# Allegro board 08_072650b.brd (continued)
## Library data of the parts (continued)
C121 C202 C203 C205 C207 C342 C347 C359 C364 C372 C376 C377 C383 C392 C399 C400 C407 C410 C417 C426 C427 C437 C446 C449 C455 C472 C473 C482-C484 C486-C489 C498-C501 C503-C507 C664 C667 C670 = CAP: Tolerance: 10; User Part Number: UPN; alternate symbols: (C0201L); part number: CAP_SM-1000PF,25V,10,E006762,C0201; tolerance: 10
C124 C141 C142 C144 C244 C246 C290 C605 = CAP: User Part Number: UPN; Tolerance: 10; alternate symbols: (C0402); part number: CAP_SM-0.1UF,16V,10,E028141,C0402; tolerance: 10
C126 = CAP: Tolerance: 5; User Part Number: UPN; alternate symbols: (C0402H22); part number: CAP_SM-160PF,50V,5,E025262,C0402H22; tolerance: 5
C127 C128 = CAP: User Part Number: UPN; Tolerance: 5; alternate symbols: (C0402); part number: CAP_SM-4700PF,10V,5,E021174,C0402; tolerance: 5
C133 C136 C193 = CAP: User Part Number: UPN; Tolerance: 20; alternate symbols: (C0402); part number: CAP_SM-10UF,6.3V,20,E025264,C0402; tolerance: 20
C135 C197 C198 C603 = CAP_SP: Tolerance: 20; User Part Number: UPN; alternate symbols: (C0805H60_SP); part number: CAP_SP_SM-22UF,16V,20,E048607,C0805H60_SP; tolerance: 20
C137-C139 C187-C189 C754-C756 = CAP: User Part Number: UPN; Tolerance: 20; alternate symbols: (C0805H60); part number: CAP_SM-47UF,6.3V,20,E025498,C0805H60; tolerance: 20
C140 C194 C601 = CAP: Tolerance: 20; User Part Number: UPN; alternate symbols: (C0402); part number: CAP_SM-10UF,6.3V,20,E025264,C0402; tolerance: 20
C153 C159 C524 C525 C614 = CAP: User Part Number: UPN; Tolerance: 10; alternate symbols: (C1206); part number: CAP_SM-10UF,16V,10,E043891,C1206; tolerance: 10
C157 = CAP: User Part Number: UPN; Tolerance: 20; alternate symbols: (C0402); part number: CAP_SM-1UF,10V,10,E028140,C0402; tolerance: 10
C158 = CAP: Tolerance: 20; User Part Number: UPN; alternate symbols: (C0402); part number: CAP_SM-1UF,10V,10,E028140,C0402; tolerance: 10
C160 C192 C617 = CAP: Tolerance: 10; User Part Number: UPN; alternate symbols: (C1206); part number: CAP_SM-10UF,16V,10,E043891,C1206; tolerance: 10
C161 C164 C170 C178 C180 C190 C528 C615 C853 = CAP: Tolerance: 20; User Part Number: UPN; alternate symbols: (C0805H53); part number: CAP_SM-100UF,6.3V,20,E029764,C0805H53; tolerance: 20
C162 C165 C529 C535 C609 = CAP: User Part Number: UPN; Tolerance: 20; alternate symbols: (C0805H53); part number: CAP_SM-100UF,6.3V,20,E029764,C0805H53; tolerance: 20
C177 C179 C181-C183 C236 C531 C534 C604 C610-C613 C616 = CAP: Tolerance: 20; User Part Number: UPN; alternate symbols: (C0805H60); part number: CAP_SM-47UF,6.3V,20,E025498,C0805H60; tolerance: 20
C184-C186 = CAP: User Part Number: UPN; Tolerance: 20; alternate symbols: (C0603); part number: CAP_SM-10UF,6.3V,20,E007143,C0603; tolerance: 20
C191 = CAP: Tolerance: 10; User Part Number: UPN; alternate symbols: (C0402); part number: CAP_SM-1UF,10V,10,E028140,C0402; tolerance: 10
C196 C602 = CAP: Tolerance: 20; User Part Number: UPN; alternate symbols: (C0402); part number: CAP_SM-4.7UF,6.3V,20,E014207,C0402; tolerance: 20
C199 C200 C249 C262-C264 C512-C516 = CAP: Tolerance: 10; User Part Number: UPN; alternate symbols: (C1210H106); part number: CAP_SM-22UF,25V,10,E054041,C1210H106; tolerance: 10
C224 C608 = CAP: User Part Number: UPN; Tolerance: 10; alternate symbols: (C0402L); part number: CAP_SM-0.01UF,50V,10,E019413,C0402; tolerance: 10
C238-C240 C757-C759 = CAP: User Part Number: UPN; Tolerance: 10; alternate symbols: (C1210H106); part number: CAP_SM-22UF,25V,10,E054041,C1210H106; tolerance: 10
C241 = CAP: User Part Number: UPN; Tolerance: 5; alternate symbols: (C0603); part number: CAP_SM-33PF,50V,5,E000396,C0603; tolerance: 5
C242 = CAP: alternate symbols: (C0603); part number: CAP_SM-20PF,250V,2,E010811,C0603; tolerance: 2
C243 = CAP: User Part Number: UPN; Tolerance: 5; alternate symbols: (C0603); part number: CAP_SM-1000PF,100V,5,E012694,C0603; tolerance: 5
C252 = CAP: alternate symbols: (C0603); part number: CAP_SM-10PF,50V,5,E031564,C0603; tolerance: 5
C255 C259 = CAP: Tolerance: 5; User Part Number: UPN; alternate symbols: (C0201L); part number: CAP_SM-10PF,25V,5,E022849,C0201; tolerance: 5
C279 C281 C283 C285 C288 C291 C294 C296 C298 C300 C302 C304 C306 C308 = CAP: Tolerance: 10; User Part Number: UPN; alternate symbols: (C0201L); part number: CAP_SM-0.01UF,25V,10,E022720,C0201; tolerance: 10
C293 C639 C640 = CAP: User Part Number: UPN; Tolerance: 10; alternate symbols: (C0402); part number: CAP_SM-1000PF,100V,10,E030277,C0402; tolerance: 10
C318 C319 = CAP: User Part Number: UPN; Tolerance: 0.25pF; alternate symbols: (C0402); part number: CAP_SM-1.5PF,50V,0.25PF,E012549,C0402; tolerance: 0.25pF
C336 C339 C346 C349 C356 C357 C361 C367 C629 = CAP: User Part Number: UPN; Tolerance: 10; alternate symbols: (C0402); part number: CAP_SM-0.1UF,10V,10,E026829,C0402; tolerance: 10
C341 C344 C362 C366 = CAP: User Part Number: UPN; Tolerance: 10; alternate symbols: (C0402); part number: CAP_SM-1000PF,16V,10,E054538,C0402; tolerance: 10
C436 C439 = CAP: User Part Number: UPN; Tolerance: 20; alternate symbols: (C0402); part number: CAP_SM-10UF,10V,20,E061425,C0402; tolerance: 20
C517 = CAP: User Part Number: UPN; Tolerance: 10; alternate symbols: (C0402); part number: CAP_SM-1UF,10V,10,E017585,C0402; tolerance: 10
C518 C520 C572 = CAP: User Part Number: UPN; Tolerance: 10; alternate symbols: (C0402); part number: CAP_SM-2200PF,50V,10,E034977,C0402; tolerance: 10
C519 C521 C573 = CAP: User Part Number: UPN; Tolerance: 1; alternate symbols: (C0402); part number: CAP_SM-150PF,50V,1,E021911,C0402; tolerance: 1
C532 C533 C536 C537 C545 C546 C646 C647 = CAP: Tolerance: 10; User Part Number: UPN; alternate symbols: (C0201L); part number: CAP_SM-0.1UF,16V,10,E039475,C0201; tolerance: 10
C553 C642 C644 = CAP: User Part Number: UPN; Tolerance: 10; alternate symbols: (C0402); part number: CAP_SM-4.7NF,16V,10,E042800,C0402; tolerance: 10
C576 = CAP: User Part Number: UPN; Tolerance: 20; alternate symbols: (C0603); part number: CAP_SM-22UF,10V,20,E035951,C0603; tolerance: 20
C577-C583 C586-C588 = CAP: Tolerance: 20; User Part Number: UPN; alternate symbols: (C1210); part number: CAP_SM-100UF,6.3V,20,E006532,C1210; tolerance: 20
C584 C585 C592-C596 C600 = CAPP3P: User Part Number: UPN; Tolerance: 20; alternate symbols: (C7343H79); part number: CAPP3P_SM-470UF,2.5V,20,E055295,C7343H79; tolerance: 20
C589-C591 C597-C599 = CAP: Tolerance: 20; User Part Number: UPN; alternate symbols: (C1206H71); part number: CAP_SM-220UF,4V,20,E045665,C1206H71; tolerance: 20
C607 = CAP: User Part Number: UPN; Tolerance: 10; alternate symbols: (C0402); part number: CAP_SM-0.22UF,16V,10,E035311,C0402; tolerance: 10
C621 C622 C760-C762 = CAP: User Part Number: UPN; Tolerance: 10; alternate symbols: (C0402); part number: CAP_SM-0.1UF,16V,10,E018707,C0402; tolerance: 10
C641 C643 C645 = CAP: User Part Number: UPN; Tolerance: 10; alternate symbols: (C0805H55); part number: CAP_SM-68NF,100V,10,E044144,C0805H55; tolerance: 10
C660 C672 C675 = CAP: User Part Number: UPN; Tolerance: 5; alternate symbols: (C0201L); part number: CAP_SM-100PF,50V,5,E023045,C0201; tolerance: 5
C661 C673 C676 = CAP: User Part Number: UPN; Tolerance: 10; alternate symbols: (C0201L); part number: CAP_SM-1000PF,25V,10,E006762,C0201; tolerance: 10
C663 C666 C669 = CAP: Tolerance: 5; User Part Number: UPN; alternate symbols: (C0201L); part number: CAP_SM-100PF,50V,5,E023045,C0201; tolerance: 5
C704 C705 = CAPP: Tolerance: 20; User Part Number: UPN; alternate symbols: (CPLSMSQ327H472); part number: CAPP_SM-180UF,25V,20,E042361,CPLSMSQ327H472; tolerance: 20
C750-C752 = CAP: User Part Number: UPN; Tolerance: 20; alternate symbols: (C0603); part number: CAP_SM-47UF,6.3V,20,E061424,C0603; tolerance: 20
C771 C772 = CAP: Tolerance: 10; User Part Number: UPN; alternate symbols: (C0402L_ALT); part number: CAP_SM-1UF,16V,10,E025259,C0402H22; tolerance: 10; signal model: DEFAULT_CAPACITOR_1E+06PF_1_2
C773-C786 C852 C854 C857 = CAP: Tolerance: 10; User Part Number: UPN; alternate symbols: (C0402L_ALT); part number: CAP_SM-1UF,10V,10,E033897,C0402; tolerance: 10
C845 C856 = CAP: Tolerance: 10; User Part Number: UPN; alternate symbols: (C0805H53); part number: CAP_SM-4.7UF,50V,10,E028468,C0805H53; tolerance: 10
C847 = CAP: Tolerance: 10; User Part Number: UPN; alternate symbols: (C0402L_ALT); part number: CAP_SM-0.1UF,16V,10,E027519,C0402; tolerance: 10
C855 = CAP: Tolerance: 20; User Part Number: UPN; alternate symbols: (C0402L_ALT); part number: CAP_SM-10UF,10V,20,E020928,C0402; tolerance: 20
C858 = CAP: Tolerance: 10; User Part Number: UPN; alternate symbols: (C0402H22); part number: CAP_SM-2.2UF,10V,10,E027484,C0402H22; tolerance: 10
C859 = CAP: User Part Number: UPN; Tolerance: 20; alternate symbols: (C0805H55); part number: CAP_SM-22UF,16V,20,E048607,C0805H55; tolerance: 20
CLK CLK_A CLK_B J3 RFOUT_2N RFOUT_2P = CNBNC2P: User Part Number: UPN; Tolerance: N/A; alternate symbols: (CNSMASQ197H161); part number: CNBNC2P_SM-85305-0232,E023859,CNSMASQ197H161; tolerance: N/A
D1 = DIO: User Part Number: UPN; Tolerance: N/A; alternate symbols: (SOD123-2); part number: DIO_SM-1N4148W-7-F,100V,N/A,E018902,SOD123-2; tolerance: N/A
D2 = DIO: User Part Number: UPN; Tolerance: N/A; alternate symbols: (DO214AC_A); part number: DIO_SM-SMAJ14A,40V,N/A,E055294,DO214AC_A; tolerance: N/A
D3 = DIOSCHOTTKY: User Part Number: UPN; Tolerance: N/A; alternate symbols: (SOD523FH33); part number: DIOSCHOTTKY_SM-CDBU0520-HF,20V,N/A,E055049,SOD523FH33; tolerance: N/A
D4 = DIOSCHOTTKY: User Part Number: UPN; Tolerance: N/A; alternate symbols: (SMA); part number: DIOSCHOTTKY_SM-MBRA340T3G,40V,N/A,E012714,SMA; tolerance: N/A
D5 = DIO: Tolerance: N/A; User Part Number: UPN; alternate symbols: (D0603H33); part number: DIO_SM-TS4148C RZG,75V,N/A,E040056,D0603H33; tolerance: N/A
D6 = DIOMMBZ5221: User Part Number: UPN; Tolerance: 5; alternate symbols: (SOT23); part number: DIOMMBZ5221_SM-BZX84-C13V,13V,5,E001199,SOT23; tolerance: 5
DS1 DS2 = DIOLED: User Part Number: UPN; Tolerance: N/A; alternate symbols: (LED0402H24); part number: DIOLED_SM-APHHS1005LSYCK/J3-PF,1.85V,N/A,E032958,LED0402H24; tolerance: N/A
DS3 DS4 DS13 DS16 DS17 DS27 = DIOLED: User Part Number: UPN; Tolerance: N/A; alternate symbols: (LED0402_A); part number: DIOLED_SM-APHHS1005LCGCK,1.9V,N/A,E032955,LED0402_A; tolerance: N/A
DS5-DS12 DS14 DS15 DS22-DS26 = DIOLED: Tolerance: N/A; User Part Number: UPN; alternate symbols: (LED0402_A); part number: DIOLED_SM-APHHS1005LCGCK,1.9V,N/A,E032955,LED0402_A; tolerance: N/A
DS18-DS21 DS31 = DIOLED: User Part Number: UPN; Tolerance: N/A; alternate symbols: (LED0402H24); part number: DIOLED_SM-APHHS1005LSECK/J3-PF,1.8V,N/A,E032957,LED0402H24; tolerance: N/A
DS29 = DIOLED: Tolerance: N/A; User Part Number: UPN; alternate symbols: (LEDSML126W63H43); part number: DIOLED_SM-SML-LX1206IW-TR,N/A,N/A,E008005,LEDSML126W63H43; tolerance: N/A
E1 E7-E14 = FERRITE: User Part Number: UPN; Tolerance: 25; alternate symbols: (L0402L); part number: FERRITE_SM-120OHM,25,E007371,L0402; tolerance: 25
E2 E3 = FERRITE: alternate symbols: (L0603_A); part number: FERRITE_SM-600OHM,25,E019039,L0603_A; tolerance: 25
E2B = FERRITE: User Part Number: UPN; Tolerance: 25; alternate symbols: (L0402); part number: FERRITE_SM-120OHM,25,E010287,L0402; tolerance: 25
E4 E5 = FERRITE: Tolerance: 25; User Part Number: UPN; alternate symbols: (L0603_A); part number: FERRITE_SM-600OHM,25,E019039,L0603_A; tolerance: 25
E15 = FERRITE: User Part Number: UPN; Tolerance: 25; alternate symbols: (L0402L); part number: FERRITE_SM-30OHM,25,E015998,L0402; tolerance: 25
E20 E23 E30 E31 = FERRITE: Tolerance: 12.5OHM; User Part Number: UPN; alternate symbols: (L1206-3); part number: FERRITE_SM-50OHM AT 100MEGHZ,12.5OHM,E040835,L1206-3; tolerance: 12.5OHM
E21 E22 = FERRITE: User Part Number: UPN; Tolerance: 25; alternate symbols: (L1206H71); part number: FERRITE_SM-470OHM AT 100MEGHZ,25,E045175,L1206H71; tolerance: 25
E24 E26 E27 = FERRITE: User Part Number: UPN; Tolerance: 12.5OHM; alternate symbols: (L1206-3); part number: FERRITE_SM-50OHM AT 100MEGHZ,12.5OHM,E040835,L1206-3; tolerance: 12.5OHM
EXT_HMCREF EXT_SYNC EXT_SYS_N EXT_SYS_P EXT_TRIG J12 J13 J17 J18 REFCLK REFN REFP = CNBNC5P: Tolerance: N/A; User Part Number: UPN; alternate symbols: (CNJOHNSON142-0701-201); part number: CNBNC5P_TH-142-0701-201,E000916,CNJOHNSON142-0701-201; tolerance: N/A
F1 = FSFUSE: Tolerance: N/A; User Part Number: UPN; alternate symbols: (F1206H46); part number: FSFUSE_SM-12A,32V,E042086,F1206H46; tolerance: N/A
FANPWM FMC12I FMC12O UNK1P8V UNK3P3V UNK12P0V = CNTP1P: Tolerance: N/A; User Part Number: UPN; alternate symbols: (CNKEY5001TP); part number: CNTP1P_TH-WHT,E005683,CNKEY5001TP; tolerance: N/A
GND1-GND8 = CNTP1P: Tolerance: N/A; User Part Number: UPN; alternate symbols: (CNKEY5001TP); part number: CNTP1P_TH-BLK,E022951,CNKEY5001TP; tolerance: N/A
JP1 = RESJMPRSHRT: Tolerance: JUMPER; User Part Number: UPN; alternate symbols: (R0402); part number: RESJMPRSHRT_SM-0,E003438,1/10W,JUMPER,R0402; tolerance: JUMPER
JP2 = RESJMPRSHRT: User Part Number: UPN; Tolerance: JUMPER; alternate symbols: (R0402); part number: RESJMPRSHRT_SM-0,E003438,1/10W,JUMPER,R0402; tolerance: JUMPER
L1 L3 L4 L10 = IND: User Part Number: UPN; Tolerance: 5; alternate symbols: (L0201_A); part number: IND_SM-1.3NH,5,E033041,L0201_A; tolerance: 5
L2 = IND: Tolerance: 30; User Part Number: UPN; alternate symbols: (L0806); part number: IND_SM-4.7UH,30,E022766,L0806; tolerance: 30
L5 = IND_V3: User Part Number: UPN; Tolerance: 10; alternate symbols: (LSML299W295H195); part number: IND_V3_SM-72NH,10,E036098,LSML299W295H195; tolerance: 10
L6 = IND: User Part Number: UPN; Tolerance: 20; alternate symbols: (L0806_DFE); part number: IND_SM-1UH,20,E042537,L0806_DFE; tolerance: 20
L8 L9 L18 = IND: User Part Number: UPN; Tolerance: 20; alternate symbols: (LSMSQ157H122); part number: IND_SM-0.13UH,20,E043494,LSMSQ157H122; tolerance: 20
L11 = IND: User Part Number: UPN; Tolerance: 20; alternate symbols: (L0603); part number: IND_SM-0.47UH,20,E039369,L0603; tolerance: 20
L15 L16 = IND: Tolerance: 5; User Part Number: UPN; alternate symbols: (L0201L); part number: IND_SM-3.6NH,5,E022818,L0201; tolerance: 5
L17 = IND: Tolerance: 20; User Part Number: UPN; alternate symbols: (L1210H47); part number: IND_SM-10UH,20,E039594,L1210H47; tolerance: 20
L19 = IND: Tolerance: 20; User Part Number: UPN; alternate symbols: (L0806_DFE); part number: IND_SM-1UH,20,E042537,L0806_DFE; tolerance: 20
L20 = IND: Tolerance: 20; User Part Number: UPN; alternate symbols: (L1008H47); part number: IND_SM-0.33UH,20,E040371,L1008H47; tolerance: 20
L21 = IND: Tolerance: 20; User Part Number: UPN; alternate symbols: (L2520H47); part number: IND_SM-0.22UH,20,E040266,L2520H47; tolerance: 20
NOREF#39 = -: Tolerance: TOL; User Part Number: UPN
P1 = CN560P_Y_M_V2: User Part Number: UPN; Tolerance: N/A; alternate symbols: (CNSAMTECASP-188588-01); part number: CN560P_Y_M_V2_SM-ASP-188588-01,E054925,CNSAMTECASP-188588-01; tolerance: N/A
P2 = CN16P_ODD_EVEN: Tolerance: N/A; User Part Number: UPN; alternate symbols: (CNHDR2X8H251); part number: CN16P_ODD_EVEN_SM-FTSH-108-01-F-DV-K,E025352,CNHDR2X8H251; tolerance: N/A
P3 = CN20P_V2: Tolerance: N/A; User Part Number: UPN; alternate symbols: (CNHDR2X10H251); part number: CN20P_V2_SM-FTSH-110-01-L-DV-K,E020976,CNHDR2X10H251; tolerance: N/A
P4 = CN5P_4PSHLD: User Part Number: UPN; Tolerance: N/A; alternate symbols: (CNFCI10103594-0001LF); part number: CN5P_4PSHLD_SM-10103594-0001LF,E032816,CNFCI10103594-0001LF; tolerance: N/A
P5 = CN4P_2PGND: User Part Number: UPN; Tolerance: N/A; alternate symbols: (CNHIROSEDF3EA-2P-2H); part number: CN4P_2PGND_SM-DF3EA-4P-2H(51),E056700,CNHIROSEDF3EA-2P-2H; tolerance: N/A
P7 = CN3P: Tolerance: N/A; User Part Number: UPN; alternate symbols: (CNSM1X3H380); part number: CN3P_SM-TSM-103-01-T-SV,E000814,CNSM1X3H380; tolerance: N/A
P18 P19 = CN2P_4GND_V2: Tolerance: N/A; User Part Number: UPN; alternate symbols: (CNSAMTECCJT-T-P-GF-RA-TH1); part number: CN2P_4GND_V2_TH-CJT-T-P-HH-RA-TH1,E058520,CNSAMTECCJT-T-P-GF-RA-TH1; tolerance: N/A
P22 = CN6P: User Part Number: UPN; Tolerance: N/A; alternate symbols: (CNHDRRA2X3H451); part number: CN6P_TH-39-30-1060,E016920,CNHDRRA2X3H451; tolerance: N/A
P23 = CN3P: User Part Number: UPN; Tolerance: N/A; alternate symbols: (CNMOLEX22-23-2031); part number: CN3P_TH-22-11-2032,E016081,CNMOLEX22-23-2031; tolerance: N/A
Q1 Q3 Q5 Q6 = TRANNMOSFET_V11: Tolerance: N/A; User Part Number: UPN; alternate symbols: (DFN6_1_3X1); part number: TRANNMOSFET_V11_SM-DMN2300UFL4-7,E017881,DFN6_1_3X1; tolerance: N/A
Q2 Q4 Q8-Q11 = TRANNMOSFET_V11: User Part Number: UPN; Tolerance: N/A; alternate symbols: (DFN6_1_3X1); part number: TRANNMOSFET_V11_SM-DMN2300UFL4-7,E017881,DFN6_1_3X1; tolerance: N/A
Q7 = TRAN2N7002: User Part Number: UPN; Tolerance: N/A; alternate symbols: (SOT523F); part number: TRAN2N7002_SM-2N7002T,E030709,SOT523F; tolerance: N/A
Q13-Q15 Q18 = TRANPMOSFET_V12: Tolerance: N/A; User Part Number: UPN; alternate symbols: (SC-70-3); part number: TRANPMOSFET_V12_SM-NTS4101PT1G,E029942,SC-70-3; tolerance: N/A
Q16 = TRANNMOSFET8P: Tolerance: N/A; User Part Number: UPN; alternate symbols: (SON8); part number: TRANNMOSFET8P_SM-BSC0504NSIATMA1,E040676,SON8; tolerance: N/A
Q17 = TRANNMOSFET_V8: User Part Number: UPN; Tolerance: N/A; alternate symbols: (SOT23); part number: TRANNMOSFET_V8_SM-SI2336DS-T1-GE3,E017134,SOT23; tolerance: N/A
Q22 = TRANPMOSFET_V12: User Part Number: UPN; Tolerance: N/A; alternate symbols: (SC-70-3); part number: TRANPMOSFET_V12_SM-NTS4101PT1G,E029942,SC-70-3; tolerance: N/A
R1 R3 R780 R781 = RES: User Part Number: UPN; Tolerance: 1; alternate symbols: (R0402); part number: RES_SM-56.2,E012977,1/10W,1,R0402; tolerance: 1
R2 R292 R296 = RES: User Part Number: UPN; Tolerance: 1; alternate symbols: (R0402); part number: RES_SM-49.9,E003750,1/10W,1,R0402; tolerance: 1
R4 R125 R325 R326 R482 = RES: User Part Number: UPN; Tolerance: 1; alternate symbols: (R0402); part number: RES_SM-1K,E003763,1/10W,1,R0402; tolerance: 1
R5 R7 R12-R15 R20 R21 R33-R36 R40-R43 R46-R48 R50 R55 R58 R74 R83 R84 R89 R90 R95 R96 R106-R109 R112-R115 R118-R121 R146 R149 R160 R162 R164-R168 R170-R181 R183 R186-R190 R193-R196 R200-R206 R208-R210 R212 R213 R215-R218 R220 R221 R224 R225 R227-R231 R233-R238 R240-R242 R245 R246 R255 R288 R290 R291 R301 R302 R306 R315-R317 R367 R371 R373 R374 R410 R413 R416-R418 R421-R424 R433 R434 R453 R495 R514 R525-R528 R534 R542 R561 R582-R584 R587-R589 R591-R594 R617-R620 R629 R633 R634 R638 R639 R643 R680 R716-R719 R761 R765-R776 R782 R783 R789 = RES: User Part Number: UPN; Tolerance: JUMPER; alternate symbols: (R0402L); part number: RES_SM-0,E003438,1/10W,JUMPER,R0402; tolerance: JUMPER
R6 R29 R64 R132 R297 = RES: User Part Number: UPN; Tolerance: 1; alternate symbols: (R0402); part number: RES_SM-100,E016329,1/10W,1,R0402; tolerance: 1
R8 R9 R22 R25 R161 R303 R318 R379 R396-R402 R420 R425-R432 R458 R469 R487 R507 R512 R535 R579 R586 R590 R595 R602-R604 R627 R628 R630 R635-R637 R687 = RES: User Part Number: UPN; Tolerance: 1; alternate symbols: (R0402); part number: RES_SM-10K,E003751,1/10W,1,R0402; tolerance: 1
R10 = RES: User Part Number: UPN; Tolerance: 1; alternate symbols: (R0402); part number: RES_SM-430,E015617,1/10W,1,R0402; tolerance: 1
R11 = RES: User Part Number: UPN; Tolerance: 1; alternate symbols: (R0402); part number: RES_SM-11K,E015614,1/10W,1,R0402; tolerance: 1
R16 R17 R723-R726 R732 R733 R740-R745 R749-R752 = RES: User Part Number: UPN; Tolerance: JUMPER; alternate symbols: (R0402); part number: RES_SM-0,E003438,1/10W,JUMPER,R0402; tolerance: JUMPER; signal model: DEFAULT_RESISTOR_0.001OHM_1_2
R18 R123 = RES: User Part Number: UPN; Tolerance: 1; alternate symbols: (R0603); part number: RES_SM-0.04,E059701,1/10W,1,R0603; tolerance: 1
R19 = RES: User Part Number: UPN; Tolerance: 1; alternate symbols: (R0402); part number: RES_SM-44.2K,E023712,1/10W,1,R0402; tolerance: 1
R23 R24 R31 R32 R38 R39 R44 R45 R85-R88 R91-R94 R97-R100 R104 R105 R110 R111 R116 R117 R148 R159 R182 R184 R185 R191 R192 R197-R199 R207 R211 R214 R219 R222 R223 R226 R232 R247 R248 R252-R254 R259-R262 R264 R265 R267 R268 R270 R271 R273 R274 R276 R277 R279-R281 R285 R404-R407 R517 R746-R748 R753-R755 R763 = RES: Tolerance: JUMPER; User Part Number: UPN; alternate symbols: (R0402L); part number: RES_SM-0,E003438,1/10W,JUMPER,R0402; tolerance: JUMPER
R26 = RES: User Part Number: UPN; Tolerance: 1; alternate symbols: (R0402); part number: RES_SM-3.01K,E027299,1/10W,1,R0402; tolerance: 1
R28 = RES: alternate symbols: (R0402); part number: RES_SM-100,E016329,1/10W,1,R0402; tolerance: 1
R49 = RES: Tolerance: JUMPER; User Part Number: UPN; alternate symbols: (R1206); part number: RES_SM-0,E004448,1/4W,JUMPER,R1206; tolerance: JUMPER
R51 = RES: alternate symbols: (R0402L); part number: RES_SM-0,E003438,1/10W,JUMPER,R0402; tolerance: JUMPER
R52 R53 = RES: User Part Number: UPN; Tolerance: 1; alternate symbols: (R0402); part number: RES_SM-1MEG,E003749,1/10W,1,R0402; tolerance: 1
R54 R778 = RES: User Part Number: UPN; Tolerance: 0.1; alternate symbols: (R0402); part number: RES_SM-38.3K,E041847,1/16W,0.1,R0402; tolerance: 0.1
R56 R57 = RES: alternate symbols: (R0402L); part number: RES_SM-150,E003455,1/10W,5,R0402; tolerance: 5
R59 = RES: User Part Number: UPN; Tolerance: 0.1; alternate symbols: (R0402); part number: RES_SM-49.9K,E058092,1/16W,0.1,R0402; tolerance: 0.1
R60 R147 R332 R336 R484 R529 R615 R616 R621 = RES: User Part Number: UPN; Tolerance: 5; alternate symbols: (R0402); part number: RES_SM-100K,E003464,1/10W,5,R0402; tolerance: 5
R61 R337 R446 R448 R490 R491 = RES: User Part Number: UPN; Tolerance: 1; alternate symbols: (R0402L); part number: RES_SM-49.9K,E004901,1/10W,1,R0402; tolerance: 1
R62 R63 R340 R386-R388 R408 R530-R532 R537 R540 R543-R545 R547 R548 R553-R555 R727 R728 = RES: User Part Number: UPN; Tolerance: 1; alternate symbols: (R0402); part number: RES_SM-10,E003768,1/10W,1,R0402; tolerance: 1
R65 R158 R344 R345 R354 R605 = RES: User Part Number: UPN; Tolerance: 1; alternate symbols: (R0402); part number: RES_SM-2.1K,E011116,1/10W,1,R0402; tolerance: 1
R66 R67 R681 = RES: Tolerance: 1; User Part Number: UPN; alternate symbols: (R0201L); part number: RES_SM-750,E025844,1/20W,1,R0201; tolerance: 1
R68 R78 R150-R157 R307-R312 R473 R474 R599 R600 R703 R708 R786 R787 = RES: Tolerance: 1; User Part Number: UPN; alternate symbols: (R0201); part number: RES_SM-10K,E004011,1/20W,1,R0201; tolerance: 1
R69 R70 R73 R471 R476 R479 R815 R816 = RES: Tolerance: 5; User Part Number: UPN; alternate symbols: (R0201); part number: RES_SM-0,E032382,1/20W,5,R0201; tolerance: 5
R71 = RES: Tolerance: 1; User Part Number: UPN; alternate symbols: (R1206H20); part number: RES_SM-0.005,E032873,1W,1,R1206H20; tolerance: 1
R72 R75-R77 R79 R80 R134 R135 R138 R139 R141 R293 R294 R321-R324 R327-R330 R419 R472 R492 R510 R511 R577 R581 R597 R598 R609 R622-R625 R645-R649 R651 R652 R654-R657 R661-R664 R667-R673 R677 R682 R683 R713 R714 = RES: Tolerance: JUMPER; User Part Number: UPN; alternate symbols: (R0201L); part number: RES_SM-0,E004015,1/20W,JUMPER,R0201; tolerance: JUMPER
R81 R370 = RES: User Part Number: UPN; Tolerance: JUMPER; alternate symbols: (R0201L); part number: RES_SM-0,E004015,1/20W,JUMPER,R0201; tolerance: JUMPER
R101 R102 R137 R304 R334 R361-R364 R644 R784 = RES: User Part Number: UPN; Tolerance: JUMPER; alternate symbols: (R1206); part number: RES_SM-0,E004448,1/4W,JUMPER,R1206; tolerance: JUMPER
R103 R385 = RES: Tolerance: 1; User Part Number: UPN; alternate symbols: (R0201L); part number: RES_SM-150,E011290,1/20W,1,R0201; tolerance: 1
R124 = RES: Tolerance: 1; User Part Number: UPN; alternate symbols: (R0402); part number: RES_SM-1K,E003763,1/10W,1,R0402; tolerance: 1
R126 = RES: User Part Number: UPN; Tolerance: 0.1; alternate symbols: (R0402); part number: RES_SM-10.2K,E040826,1/16W,0.1,R0402; tolerance: 0.1
R127 R515 = RES: Tolerance: 0.1; User Part Number: UPN; alternate symbols: (R0402); part number: RES_SM-10.2K,E040826,1/16W,0.1,R0402; tolerance: 0.1
R128 = RES: User Part Number: UPN; Tolerance: 1; alternate symbols: (R0402L); part number: RES_SM-30.1K,E010069,1/10W,1,R0402; tolerance: 1
R129 = RES: Tolerance: 1; User Part Number: UPN; alternate symbols: (R0402L); part number: RES_SM-30.1K,E010069,1/10W,1,R0402; tolerance: 1
R130 = RES: User Part Number: UPN; Tolerance: 1; alternate symbols: (R0402L); part number: RES_SM-64.9K,E010879,1/10W,1,R0402; tolerance: 1
R131 = RES: Tolerance: 1; User Part Number: UPN; alternate symbols: (R0402L); part number: RES_SM-64.9K,E010879,1/10W,1,R0402; tolerance: 1
R133 = RES: User Part Number: UPN; Tolerance: 0.1; alternate symbols: (R0402); part number: RES_SM-14K,E042356,1/16W,0.1,R0402; tolerance: 0.1
R136 R239 R243 R244 R249-R251 R256-R258 R263 R266 R269 R272 R275 R278 R282-R284 R298-R300 R319 R320 R389-R395 R488 R489 R498 R499 R501 R502 R505 = RES: Tolerance: 1; User Part Number: UPN; alternate symbols: (R0201NC); part number: RES_SM-100,E007239,1/20W,1,R0201; tolerance: 1
R140 = RES: User Part Number: UPN; Tolerance: 0.5; alternate symbols: (R0402); part number: RES_SM-137K,E025681,1/16W,0.5,R0402; tolerance: 0.5
R142 R143 R653 R679 = RES: User Part Number: UPN; Tolerance: 1; alternate symbols: (R0402L); part number: RES_SM-5.49K,E020564,1/10W,1,R0402; tolerance: 1
R144 = RES: Tolerance: 0.1; User Part Number: UPN; alternate symbols: (R0402); part number: RES_SM-14K,E042356,1/16W,0.1,R0402; tolerance: 0.1
R145 = RES: Tolerance: 1; User Part Number: UPN; alternate symbols: (R0402); part number: RES_SM-178K,E048615,1/10W,1,R0402; tolerance: 1
R163 = RES: User Part Number: UPN; Tolerance: 1; alternate symbols: (R0402); part number: RES_SM-51K,E013080,1/10W,1,R0402; tolerance: 1
R169 = RES: User Part Number: UPN; Tolerance: 1; alternate symbols: (R0402); part number: RES_SM-78.7K,E006344,1/10W,1,R0402; tolerance: 1
R286 = RES: alternate symbols: (R0603); part number: RES_SM-931,E011038,1/10W,1,R0603; tolerance: 1
R287 = RES: User Part Number: UPN; Tolerance: 1; alternate symbols: (R0603); part number: RES_SM-30,E028547,1/10W,1,R0603; tolerance: 1
R289 = RES: User Part Number: UPN; Tolerance: 1; alternate symbols: (R0603); part number: RES_SM-324,E004034,1/10W,1,R0603; tolerance: 1
R295 = RES: User Part Number: UPN; Tolerance: 0.1; alternate symbols: (R0402); part number: RES_SM-200,E006431,1/16W,0.1,R0402; tolerance: 0.1
R305 = RES: User Part Number: UPN; Tolerance: 0.1; alternate symbols: (R0402); part number: RES_SM-62,E026752,1/16W,0.1,R0402; tolerance: 0.1
R313 R314 = RES: User Part Number: UPN; Tolerance: 0.1; alternate symbols: (R0402); part number: RES_SM-464,E050710,1/16W,0.1,R0402; tolerance: 0.1
R331 R333 R338 R339 R342 R343 R357-R360 R520 = RES: Tolerance: 5; User Part Number: UPN; alternate symbols: (R0402); part number: RES_SM-100K,E003464,1/10W,5,R0402; tolerance: 5
R335 = RES: Tolerance: 1; User Part Number: UPN; alternate symbols: (R0402); part number: RES_SM-78.7K,E006344,1/10W,1,R0402; tolerance: 1
R341 R522 R549 R552 R764 = RES: Tolerance: 1; User Part Number: UPN; alternate symbols: (R0402); part number: RES_SM-10,E003768,1/10W,1,R0402; tolerance: 1
R346-R353 R355 R356 = RES: Tolerance: 1; User Part Number: UPN; alternate symbols: (R0402); part number: RES_SM-2.1K,E011116,1/10W,1,R0402; tolerance: 1
R365 = RES: User Part Number: UPN; Tolerance: 1; alternate symbols: (R1206); part number: RES_SM-0.003,E019911,1W,1,R1206; tolerance: 1
R366 = RES: Tolerance: 1; User Part Number: UPN; alternate symbols: (R1206); part number: RES_SM-0.003,E019911,1W,1,R1206; tolerance: 1
R368 = RES: User Part Number: UPN; Tolerance: 1; alternate symbols: (R0402); part number: RES_SM-24.9K,E007443,1/10W,1,R0402; tolerance: 1
R369 = RES: User Part Number: UPN; Tolerance: JUMPER; alternate symbols: (R0402); part number: RES_SM-0,E030866,1/5W,JUMPER,R0402; tolerance: JUMPER
R372 = RES: User Part Number: UPN; Tolerance: 1; alternate symbols: (R0402); part number: RES_SM-34.8K,E020912,1/10W,1,R0402; tolerance: 1
R380 R382 = RES: User Part Number: UPN; Tolerance: 0.1; alternate symbols: (R0402); part number: RES_SM-147K,E064075,1/10W,0.1,R0402; tolerance: 0.1
R381 = RES: Tolerance: 0.1; User Part Number: UPN; alternate symbols: (R0201); part number: RES_SM-196K,E064035,1/20W,0.1,R0201; tolerance: 0.1
R403 R519 = RES: Tolerance: 1; User Part Number: UPN; alternate symbols: (R0402); part number: RES_SM-10K,E003751,1/10W,1,R0402; tolerance: 1
R409 R411 R412 R516 R550 R779 = RES: User Part Number: UPN; Tolerance: JUMPER; alternate symbols: (R1206); part number: RES_SM-0,E014206,3/4W,JUMPER,R1206; tolerance: JUMPER
R415 R758 R760 = RES: User Part Number: UPN; Tolerance: 1; alternate symbols: (R0805); part number: RES_SM-0.002,E035347,1/2W,1,R0805; tolerance: 1
R435-R440 = RES: User Part Number: UPN; Tolerance: 1; alternate symbols: (R0402); part number: RES_SM-14.3K,E019974,1/16W,1,R0402; tolerance: 1
R441 R442 R449 = RES: User Part Number: UPN; Tolerance: 1; alternate symbols: (R0402); part number: RES_SM-32.4K,E017609,1/10W,1,R0402; tolerance: 1
R443 R444 = RES: User Part Number: UPN; Tolerance: 1; alternate symbols: (R0402); part number: RES_SM-787,E029029,1/10W,1,R0402; tolerance: 1
R445 = RES: User Part Number: UPN; Tolerance: 1; alternate symbols: (R0402); part number: RES_SM-1.65K,E054927,1/10W,1,R0402; tolerance: 1
R447 = RES: User Part Number: UPN; Tolerance: 1; alternate symbols: (R0402); part number: RES_SM-2.43K,E004028,1/10W,1,R0402; tolerance: 1
R450 = RES: User Part Number: UPN; Tolerance: 1; alternate symbols: (R0402); part number: RES_SM-22.6K,E020076,1/10W,1,R0402; tolerance: 1
R451 = RES: Tolerance: 1; User Part Number: UPN; alternate symbols: (R1206-2); part number: RES_SM-0.03,E033615,1/2W,1,R1206-2; tolerance: 1
R452 = RES: Tolerance: 1; User Part Number: UPN; alternate symbols: (R1206-2); part number: RES_SM-0.3,E025631,1/2W,1,R1206-2; tolerance: 1
R454 = RES: Tolerance: 1; User Part Number: UPN; alternate symbols: (R0402); part number: RES_SM-28K,E010020,1/10W,1,R0402; tolerance: 1
R455 = RES: Tolerance: 1; User Part Number: UPN; alternate symbols: (R0402); part number: RES_SM-3.01K,E027299,1/10W,1,R0402; tolerance: 1
R456 = RES: Tolerance: 1; User Part Number: UPN; alternate symbols: (R0402); part number: RES_SM-33.2K,E020578,1/16W,1,R0402; tolerance: 1
R457 R546 = RES: Tolerance: JUMPER; User Part Number: UPN; alternate symbols: (R1206); part number: RES_SM-0,E014206,3/4W,JUMPER,R1206; tolerance: JUMPER
R459 R468 = RES: User Part Number: UPN; Tolerance: 5; alternate symbols: (R0402); part number: RES_SM-300,E003444,1/10W,5,R0402; tolerance: 5
R460-R467 = RES: Tolerance: 5; User Part Number: UPN; alternate symbols: (R0402); part number: RES_SM-300,E003444,1/10W,5,R0402; tolerance: 5
R470 = RES: User Part Number: UPN; Tolerance: 5; alternate symbols: (R0201); part number: RES_SM-0,E032382,1/20W,5,R0201; tolerance: 5
R483 = RES: User Part Number: UPN; Tolerance: 1; alternate symbols: (R0402); part number: RES_SM-0.2,E022868,1/6W,1,R0402; tolerance: 1
R485 = RES: User Part Number: UPN; Tolerance: 1; alternate symbols: (R0402); part number: RES_SM-13.7K,E054720,1/10W,1,R0402; tolerance: 1
R486 = RES: User Part Number: UPN; Tolerance: 1; alternate symbols: (R0402); part number: RES_SM-18,E013168,1/10W,1,R0402; tolerance: 1
R493 R494 R506 R524 R562 R756 R777 = RES: User Part Number: UPN; Tolerance: 1; alternate symbols: (R1206); part number: RES_SM-0.001,E019910,1W,1,R1206; tolerance: 1
R496 = RES: User Part Number: UPN; Tolerance: 1; alternate symbols: (R0603); part number: RES_SM-0.05,E057430,1/10W,1,R0603; tolerance: 1
R497 = RES: User Part Number: UPN; Tolerance: 0.1; alternate symbols: (R0402); part number: RES_SM-25.5K,E019320,1/16W,0.1,R0402; tolerance: 0.1
R500 = RES: User Part Number: UPN; Tolerance: 1; alternate symbols: (R0402); part number: RES_SM-115K,E025179,1/10W,1,R0402; tolerance: 1
R504 = RES: User Part Number: UPN; Tolerance: 1; alternate symbols: (R0402); part number: RES_SM-53.6K,E023305,1/16W,1,R0402; tolerance: 1
R518 = RES: Tolerance: 1; User Part Number: UPN; alternate symbols: (R0402); part number: RES_SM-47K,E008189,1/10W,1,R0402; tolerance: 1
R521 = RES: Tolerance: 0.1; User Part Number: UPN; alternate symbols: (R0402); part number: RES_SM-49.9K,E033966,1/16W,0.1,R0402; tolerance: 0.1
R523 = RES: Tolerance: 1; User Part Number: UPN; alternate symbols: (R1206); part number: RES_SM-0.005,E059700,1W,1,R1206; tolerance: 1
R533 = RES: User Part Number: UPN; Tolerance: 0.1; alternate symbols: (R0402); part number: RES_SM-332,E028009,1/16W,0.1,R0402; tolerance: 0.1
R536 = RES: User Part Number: UPN; Tolerance: 1; alternate symbols: (R0402); part number: RES_SM-40.2K,E006353,1/10W,1,R0402; tolerance: 1
R538 = RES: User Part Number: UPN; Tolerance: 0.1; alternate symbols: (R0603); part number: RES_SM-143K,E020916,1/10W,0.1,R0603; tolerance: 0.1
R539 = RES: User Part Number: UPN; Tolerance: 1; alternate symbols: (R0402); part number: RES_SM-309K,E036090,1/10W,1,R0402; tolerance: 1
R541 = RES: User Part Number: UPN; Tolerance: 1; alternate symbols: (R0402); part number: RES_SM-0.1,E017078,1/6W,1,R0402; tolerance: 1
R551 = RES: Tolerance: 0.1; User Part Number: UPN; alternate symbols: (R0402); part number: RES_SM-332,E028009,1/16W,0.1,R0402; tolerance: 0.1
R556 R559 R560 R563-R576 = RES: Tolerance: 5; User Part Number: UPN; alternate symbols: (R0201); part number: RES_SM-4.7,E019116,1/20W,5,R0201; tolerance: 5
R557 R558 = RES: User Part Number: UPN; Tolerance: 5; alternate symbols: (R0201); part number: RES_SM-4.7,E019116,1/20W,5,R0201; tolerance: 5
R578 R596 R606-R608 R631 R658 R684 R704-R707 = RES: User Part Number: UPN; alternate symbols: (R0201L); part number: RES_SM-1,E014056,1/20W,1,R0201
R585 = RES: User Part Number: UPN; Tolerance: 1; alternate symbols: (R0402); part number: RES_SM-909,E007340,1/10W,1,R0402; tolerance: 1
R601 R632 R659 R660 = RES: Tolerance: 1; User Part Number: UPN; alternate symbols: (R0201L); part number: RES_SM-49.9K,E018324,1/20W,1,R0201; tolerance: 1
R626 = RES: User Part Number: UPN; Tolerance: 5; alternate symbols: (R0402); part number: RES_SM-1K,E020936,1/16W,5,R0402; tolerance: 5
R640-R642 = RES: User Part Number: UPN; Tolerance: 1; alternate symbols: (R0402L); part number: RES_SM-665,E006717,1/16W,1,R0402; tolerance: 1
R650 R665 R666 R676 = RES: Tolerance: 1; User Part Number: UPN; alternate symbols: (R0201NC); part number: RES_SM-1K,E004010,1/20W,1,R0201; tolerance: 1
R685 R686 = RES: User Part Number: UPN; Tolerance: 1; alternate symbols: (R0201L); part number: RES_SM-49.9K,E018324,1/20W,1,R0201; tolerance: 1
R709 R710 = RES: User Part Number: UPN; Tolerance: 0.1; alternate symbols: (R0402); part number: RES_SM-50,E016309,1/20W,0.1,R0402; tolerance: 0.1
R711 R712 = RES: User Part Number: UPN; Tolerance: 0.1; alternate symbols: (R0402); part number: RES_SM-100K,E060336,1/10W,0.1,R0402; tolerance: 0.1
R715 R735 R788 = RES: User Part Number: UPN; Tolerance: 1; alternate symbols: (R0402); part number: RES_SM-100,E003760,1/16W,1,R0402; tolerance: 1
R720 R721 = RES: User Part Number: UPN; Tolerance: 1; alternate symbols: (R0402); part number: RES_SM-39.2,E023111,1/10W,1,R0402; tolerance: 1
R722 = RES: User Part Number: UPN; Tolerance: 5; alternate symbols: (R0402L); part number: RES_SM-100,E003443,1/10W,5,R0402; tolerance: 5
R729-R731 = RES: Tolerance: 5; User Part Number: UPN; alternate symbols: (R0201); part number: RES_SM-0.1,E029900,1/10W,5,R0201; tolerance: 5
R734 = RES: User Part Number: UPN; Tolerance: 5; alternate symbols: (R0402); part number: RES_SM-330,E003462,1/10W,5,R0402; tolerance: 5
R736-R739 = RES: Tolerance: 1; User Part Number: UPN; alternate symbols: (R0402L_ALT); part number: RES_SM-10K,E003751,1/10W,1,R0402; tolerance: 1
R757 R759 R762 = RES: Tolerance: 1; User Part Number: UPN; alternate symbols: (R0402L); part number: RES_SM-665,E006717,1/16W,1,R0402; tolerance: 1
R794 R810 = RES: User Part Number: UPN; Tolerance: 1; alternate symbols: (R0402); part number: RES_SM-100K,E017855,1/16W,1,R0402; tolerance: 1
R797 = RES: Tolerance: 1; User Part Number: UPN; alternate symbols: (R0402L_ALT); part number: RES_SM-48.7K,E025172,1/10W,1,R0402; tolerance: 1
R807 = RES: User Part Number: UPN; Tolerance: 1; alternate symbols: (R0402); part number: RES_SM-76.8K,E006340,1/10W,1,R0402; tolerance: 1
R808 = RES: Tolerance: 1; User Part Number: UPN; alternate symbols: (R0402L_ALT); part number: RES_SM-280K,E019616,1/16W,1,R0402; tolerance: 1
R809 = RES: Tolerance: 1; User Part Number: UPN; alternate symbols: (R0402L_ALT); part number: RES_SM-160K,E013603,1/10W,1,R0402; tolerance: 1
R811 = RES: User Part Number: UPN; Tolerance: JUMPER; alternate symbols: (R0402); part number: RES_SM-0,E003438,1/10W,JUMPER,R0402; tolerance: JUMPER
S1-S3 = SWSPST4PIN_V2: User Part Number: UPN; Tolerance: N/A; alternate symbols: (SWSMSQ197H165-2); part number: SWSPST4PIN_V2_SM-7914G-1-000E,E014175,SWSMSQ197H165-2; tolerance: N/A
S4 = SWDPDT_2GND: User Part Number: UPN; Tolerance: N/A; alternate symbols: (SWTHRAL500W900H450); part number: SWDPDT_2GND_TH-1201M2S3AQE2,E018708,SWTHRAL500W900H450; tolerance: N/A
S5 = SWITCH4: User Part Number: UPN; Tolerance: N/A; alternate symbols: (SWDIP8H335); part number: SWITCH4_TH-CTS206-4,E004560,SWDIP8H335; tolerance: N/A
T1 = XFMRBAL0XXX: Tolerance: N/A; User Part Number: UPN; alternate symbols: (TSML500W200H110); part number: XFMRBAL0XXX_SM-BAL-0020SLG,E046080,TSML500W200H110; tolerance: N/A
T1WA T1WB T1XA T1XB T1YA T1YB T1ZA T1ZB T2 T3 = XFMRBAL0XXX: User Part Number: UPN; Tolerance: N/A; alternate symbols: (TSML500W200H110); part number: XFMRBAL0XXX_SM-BAL-0020SLG,E046080,TSML500W200H110; tolerance: N/A
T4 = XFMRTCMXXXX_V4: Tolerance: N/A; User Part Number: UPN; alternate symbols: (TSML150W160H160); part number: XFMRTCMXXXX_V4_SM-TCM2-43X+,E018599,TSML150W160H160; tolerance: N/A
TP1-TP13 TP15-TP17 TP19-TP31 TP33-TP35 TP39-TP41 TP58 TP59 TP64 TP65 UNK80A_V0 UNK80B_V4 = NCTESTPAD: Tolerance: N/A; User Part Number: UPN; alternate symbols: (TPSMC30); part number: NCTESTPAD_SM-TESTPAD,E012884,TPSMC30; tolerance: N/A
TP18 TP32 TP36 TP37 = NCTESTPAD: User Part Number: UPN; Tolerance: N/A; alternate symbols: (TPSMC30); part number: NCTESTPAD_SM-TESTPAD,E012884,TPSMC30; tolerance: N/A
TP42-TP45 TP48-TP57 TP60-TP63 TP78 = NCTESTPAD: Tolerance: N/A; User Part Number: UPN; alternate symbols: (TPSMC40); part number: NCTESTPAD_SM-TESTPAD,E019801,TPSMC40; tolerance: N/A
TP46 TP47 = NCTESTPAD: User Part Number: UPN; Tolerance: N/A; alternate symbols: (TPSMC40); part number: NCTESTPAD_SM-TESTPAD,E019801,TPSMC40; tolerance: N/A
U1 U5 = ADLTM4702: User Part Number: UPN; Tolerance: N/A; alternate symbols: (BGA49H211); part number: ADLTM4702_SM-LTM4702EY#PBF,E046178,BGA49H211; tolerance: N/A
U1A = AD9088_8T8R_SE_B0: User Part Number: UPN; Tolerance: N/A; alternate symbols: (BGA899); part number: AD9088_8T8R_SE_B0_SM-AD9088_8T8R_SE_B0,E063863,BGA899; tolerance: N/A
U1B = ADHMC7044: User Part Number: UPN; Tolerance: N/A; alternate symbols: (QFN68_10X10_PAD6_3X6_3); part number: ADHMC7044_SM-HMC7044LP10BE,E021514,QFN68_10X10_PAD6_3X6_3; tolerance: N/A
U2 = ADLTC6955: Tolerance: N/A; User Part Number: UPN; alternate symbols: (QFN52_8X7_PAD6_45X5_41); part number: ADLTC6955_SM-LTC6955IUKG#PBF,E059501,QFN52_8X7_PAD6_45X5_41; tolerance: N/A
U3 U54 = ADP124: User Part Number: UPN; Tolerance: N/A; alternate symbols: (QFN8_2X2_PAD1_6X1); part number: ADP124_SM-ADP124ACPZ-1.8,E015976,QFN8_2X2_PAD1_6X1; tolerance: N/A
U4 = LINLT3045_V2: Tolerance: 10; User Part Number: UPN; alternate symbols: (DFN10_3X3_PAD2_38X1_64); part number: LINLT3045_V2_SM-LT3045EDD#PBF,E031738,DFN10_3X3_PAD2_38X1_64; tolerance: 10
U6 U40 = LINLTM8074: User Part Number: UPN; Tolerance: N/A; alternate symbols: (BGA25_4X4); part number: LINLTM8074_SM-LTM8074EY#PBF,E034121,BGA25_4X4; tolerance: N/A
U7 U34 = ADLTM4709: User Part Number: UPN; Tolerance: N/A; alternate symbols: (BGA98_12X6); part number: ADLTM4709_SM-LTM4709HY,E050426,BGA98_12X6; tolerance: N/A
U8 U52 = ADLTM4709: Tolerance: N/A; User Part Number: UPN; alternate symbols: (BGA98_12X6); part number: ADLTM4709_SM-LTM4709HY,E050426,BGA98_12X6; tolerance: N/A
U9 = LINLT3094: User Part Number: UPN; Tolerance: N/A; alternate symbols: (DFN12_3X3_PAD2_38X1_65); part number: LINLT3094_SM-LT3094EDD#PBF,E033630,DFN12_3X3_PAD2_38X1_65; tolerance: N/A
U10 = LINLT3094: Tolerance: N/A; User Part Number: UPN; alternate symbols: (DFN12_3X3_PAD2_38X1_65); part number: LINLT3094_SM-LT3094EDD#PBF,E033630,DFN12_3X3_PAD2_38X1_65; tolerance: N/A
U11 = ADLTC2980_24: User Part Number: UPN; Tolerance: N/A; alternate symbols: (BGA210_16_9X8_1); part number: ADLTC2980_24_SM-LTC2980IY-24#PBF,E053976,BGA210_16_9X8_1; tolerance: N/A
U12-U18 = ADG772: User Part Number: UPN; Tolerance: N/A; alternate symbols: (QFN10_1_6X1_3); part number: ADG772_SM-ADG772BCPZ,E010354,QFN10_1_6X1_3; tolerance: N/A
U19 = ADG772: Tolerance: N/A; User Part Number: UPN; alternate symbols: (QFN10_1_6X1_3); part number: ADG772_SM-ADG772BCPZ,E010354,QFN10_1_6X1_3; tolerance: N/A
U20 = ICM24CXX: Tolerance: N/A; User Part Number: UPN; alternate symbols: (TSSOP8); part number: ICM24CXX_SM-M24C02-FDW6TP,E031427,TSSOP8; tolerance: N/A
U21 = DIO6P: User Part Number: UPN; Tolerance: N/A; alternate symbols: (UQFN6_1_45X1); part number: DIO6P_SM-USBULC6-2M6,N/A,N/A,E008202,UQFN6_1_45X1; tolerance: N/A
U22 = ICCP2105: Tolerance: N/A; User Part Number: UPN; alternate symbols: (QFN24_4X4_PAD2_7X2_7); part number: ICCP2105_SM-CP2105-F01-GM,E035946,QFN24_4X4_PAD2_7X2_7; tolerance: N/A
U23 U24 U41 = FXLA104: Tolerance: N/A; User Part Number: UPN; alternate symbols: (MLP12_1_8X1_8); part number: FXLA104_SM-FXLA104UM12X,E017574,MLP12_1_8X1_8; tolerance: N/A
U25-U29 U42-U48 = FXLA104: User Part Number: UPN; Tolerance: N/A; alternate symbols: (MLP12_1_8X1_8); part number: FXLA104_SM-FXLA104UM12X,E017574,MLP12_1_8X1_8; tolerance: N/A
U30 = ADF4382: alternate symbols: (LGA48_7X7_PAD2_375X2_375); part number: ADF4382_SM-ADF4382,E049960,LGA48_7X7_PAD2_375X2_375; tolerance: N/A
U31 U36 = ADLTM4702: Tolerance: N/A; User Part Number: UPN; alternate symbols: (BGA49H211); part number: ADLTM4702_SM-LTM4702EY#PBF,E046178,BGA49H211; tolerance: N/A
U32 = ADLTM8051: User Part Number: UPN; Tolerance: N/A; alternate symbols: (BGA91_11_25X6_25); part number: ADLTM8051_SM-LTM8051EY#PBF,E042396,BGA91_11_25X6_25; tolerance: N/A
U33 = ADLTM4681: Tolerance: N/A; User Part Number: UPN; alternate symbols: (BGA330_22X15H337); part number: ADLTM4681_SM-LTM4681IY#PBF,E054666,BGA330_22X15H337; tolerance: N/A
U35 = 7416244_V3: Tolerance: N/A; User Part Number: UPN; alternate symbols: (TSSOP48); part number: 7416244_V3_SM-MC74LCX16244DTG,E054962,TSSOP48; tolerance: N/A
U37 = LINLT6658: User Part Number: UPN; Tolerance: N/A; alternate symbols: (DFN16_4X3_PAD3_3X1_7); part number: LINLT6658_SM-LT6658AHDE-1.2#TRPBF,E049551,DFN16_4X3_PAD3_3X1_7; tolerance: N/A
U38 = LINLT3045_V2: User Part Number: UPN; Tolerance: 10; alternate symbols: (DFN10_3X3_PAD2_38X1_64); part number: LINLT3045_V2_SM-LT3045EDD#PBF,E031738,DFN10_3X3_PAD2_38X1_64; tolerance: 10
U39 = ADLTC4210: User Part Number: UPN; Tolerance: N/A; alternate symbols: (TSOT23_6); part number: ADLTC4210_SM-LTC4210-2IS6#TRMPBF,E043704,TSOT23_6; tolerance: N/A
U49 = XTALVCXO6P_V3: Tolerance: N/A; User Part Number: UPN; alternate symbols: (YSML560W360H210_6P); part number: XTALVCXO6P_V3_SM-125 MHZ,E062858,YSML560W360H210_6P; tolerance: N/A
U50 = 741G04: Tolerance: N/A; User Part Number: UPN; alternate symbols: (SC70-5); part number: 741G04_SM-SN74LVC1GU04DCKT,E057527,SC70-5; tolerance: N/A
U51 = ADF4030: User Part Number: UPN; Tolerance: N/A; alternate symbols: (LGA48_7X7_PAD2_375X2_375); part number: ADF4030_SM-ADF4030,E058509,LGA48_7X7_PAD2_375X2_375; tolerance: N/A
U53 = ADP7112: User Part Number: UPN; Tolerance: N/A; alternate symbols: (WLCSP6_B); part number: ADP7112_SM-ADP7112ACBZ-5.0-R7,E025018,WLCSP6_B; tolerance: N/A
U72 = LINLTM8053: Tolerance: N/A; User Part Number: UPN; alternate symbols: (BGA48H139); part number: LINLTM8053_SM-LTM8053EY#PBF,E031218,BGA48H139; tolerance: N/A
U73 = ADP7159_V2: Tolerance: N/A; User Part Number: UPN; alternate symbols: (DFN10_3X3_PAD2_38X1_64); part number: ADP7159_V2_SM-ADP7159ACPZ-04-R7,E029076,DFN10_3X3_PAD2_38X1_64; tolerance: N/A
U74 = ADP7112: User Part Number: UPN; Tolerance: N/A; alternate symbols: (WLCSP6_B); part number: ADP7112_SM-ADP7112ACBZ-1.8-R7,E024097,WLCSP6_B; tolerance: N/A
Y1 Y3 = XTALCPP: Tolerance: N/A; User Part Number: UPN; alternate symbols: (LCC4H210); part number: XTALCPP_SM-125MEGHZ,E017655,LCC4H210; tolerance: N/A

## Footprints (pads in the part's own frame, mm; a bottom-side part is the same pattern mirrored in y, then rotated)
BGA25_4X4
  round 0.33 smd: A1(-1.3,-1.3) A2(-1.3,-0.65) A3(-1.3,0) A4(-1.3,0.65) A5(-1.3,1.3) B1(-0.65,-1.3) B2(-0.65,-0.65) B3(-0.65,0) B4(-0.65,0.65) B5(-0.65,1.3) C1(0,-1.3) C2(0,-0.65) C3(0,0) C4(0,0.65) C5(0,1.3) D1(0.65,-1.3) D2(0.65,-0.65) D3(0.65,0) D4(0.65,0.65) D5(0.65,1.3) E1(1.3,-1.3) E2(1.3,-0.65) E3(1.3,0) E4(1.3,0.65) E5(1.3,1.3)
BGA48H139
  round 0.483 smd: A1(-3.5,-2.5) A2(-3.5,-1.5) A3(-3.5,-0.5) A4(-3.5,0.5) A5(-3.5,1.5) A6(-3.5,2.5) B1(-2.5,-2.5) B2(-2.5,-1.5) B3(-2.5,-0.5) B4(-2.5,0.5) B5(-2.5,1.5) B6(-2.5,2.5) C1(-1.5,-2.5) C2(-1.5,-1.5) C3(-1.5,-0.5) C4(-1.5,0.5) C5(-1.5,1.5) C6(-1.5,2.5) D1(-0.5,-2.5) D2(-0.5,-1.5) D3(-0.5,-0.5) D4(-0.5,0.5) D5(-0.5,1.5) D6(-0.5,2.5) E1(0.5,-2.5) E2(0.5,-1.5) E3(0.5,-0.5) E4(0.5,0.5) E5(0.5,1.5) E6(0.5,2.5) F1(1.5,-2.5) F2(1.5,-1.5) F3(1.5,-0.5) F4(1.5,0.5) F5(1.5,1.5) F6(1.5,2.5) G1(2.5,-2.5) G2(2.5,-1.5) G3(2.5,-0.5) G4(2.5,0.5) G5(2.5,1.5) G6(2.5,2.5) H1(3.5,-2.5) H2(3.5,-1.5) H3(3.5,-0.5) H4(3.5,0.5) H5(3.5,1.5) H6(3.5,2.5)
BGA49H211
  round 0.406 smd: A1(-2.4,-2.4) A2(-2.4,-1.6) A3(-2.4,-0.8) A4(-2.4,0) A5(-2.4,0.8) A6(-2.4,1.6) A7(-2.4,2.4) B1(-1.6,-2.4) B2(-1.6,-1.6) B3(-1.6,-0.8) B4(-1.6,0) B5(-1.6,0.8) B6(-1.6,1.6) B7(-1.6,2.4) C1(-0.8,-2.4) C2(-0.8,-1.6) C3(-0.8,-0.8) C4(-0.8,0) C5(-0.8,0.8) C6(-0.8,1.6) C7(-0.8,2.4) D1(0,-2.4) D2(0,-1.6) D3(0,-0.8) D4(0,0) D5(0,0.8) D6(0,1.6) D7(0,2.4) E1(0.8,-2.4) E2(0.8,-1.6) E3(0.8,-0.8) E4(0.8,0) E5(0.8,0.8) E6(0.8,1.6) E7(0.8,2.4) F1(1.6,-2.4) F2(1.6,-1.6) F3(1.6,-0.8) F4(1.6,0) F5(1.6,0.8) F6(1.6,1.6) F7(1.6,2.4) G1(2.4,-2.4) G2(2.4,-1.6) G3(2.4,-0.8) G4(2.4,0) G5(2.4,0.8) G6(2.4,1.6) G7(2.4,2.4)
BGA91_11_25X6_25
  round 0.406 smd: A1(-4.8,-2.4) A2(-4.8,-1.6) A3(-4.8,-0.8) A4(-4.8,0) A5(-4.8,0.8) A6(-4.8,1.6) A7(-4.8,2.4) B1(-4,-2.4) B2(-4,-1.6) B3(-4,-0.8) B4(-4,0) B5(-4,0.8) B6(-4,1.6) B7(-4,2.4) C1(-3.2,-2.4) C2(-3.2,-1.6) C3(-3.2,-0.8) C4(-3.2,0) C5(-3.2,0.8) C6(-3.2,1.6) C7(-3.2,2.4) D1(-2.4,-2.4) D2(-2.4,-1.6) D3(-2.4,-0.8) D4(-2.4,0) D5(-2.4,0.8) D6(-2.4,1.6) D7(-2.4,2.4) E1(-1.6,-2.4) E2(-1.6,-1.6) E3(-1.6,-0.8) E4(-1.6,0) E5(-1.6,0.8) E6(-1.6,1.6) E7(-1.6,2.4) F1(-0.8,-2.4) F2(-0.8,-1.6) F3(-0.8,-0.8) F4(-0.8,0) F5(-0.8,0.8) F6(-0.8,1.6) F7(-0.8,2.4) G1(0,-2.4) G2(0,-1.6) G3(0,-0.8) G4(0,0) G5(0,0.8) G6(0,1.6) G7(0,2.4) H1(0.8,-2.4) H2(0.8,-1.6) H3(0.8,-0.8) H4(0.8,0) H5(0.8,0.8) H6(0.8,1.6) H7(0.8,2.4) J1(1.6,-2.4) J2(1.6,-1.6) J3(1.6,-0.8) J4(1.6,0) J5(1.6,0.8) J6(1.6,1.6) J7(1.6,2.4) K1(2.4,-2.4) K2(2.4,-1.6) K3(2.4,-0.8) K4(2.4,0) K5(2.4,0.8) K6(2.4,1.6) K7(2.4,2.4) L1(3.2,-2.4) L2(3.2,-1.6) L3(3.2,-0.8) L4(3.2,0) L5(3.2,0.8) L6(3.2,1.6) L7(3.2,2.4) M1(4,-2.4) M2(4,-1.6) M3(4,-0.8) M4(4,0) M5(4,0.8) M6(4,1.6) M7(4,2.4) N1(4.8,-2.4) N2(4.8,-1.6) N3(4.8,-0.8) N4(4.8,0) N5(4.8,0.8) N6(4.8,1.6) N7(4.8,2.4)
BGA98_12X6
  round 0.406 smd: A1(-5.2,-2.4) A2(-5.2,-1.6) A3(-5.2,-0.8) A4(-5.2,0) A5(-5.2,0.8) A6(-5.2,1.6) A7(-5.2,2.4) B1(-4.4,-2.4) B2(-4.4,-1.6) B3(-4.4,-0.8) B4(-4.4,0) B5(-4.4,0.8) B6(-4.4,1.6) B7(-4.4,2.4) C1(-3.6,-2.4) C2(-3.6,-1.6) C3(-3.6,-0.8) C4(-3.6,0) C5(-3.6,0.8) C6(-3.6,1.6) C7(-3.6,2.4) D1(-2.8,-2.4) D2(-2.8,-1.6) D3(-2.8,-0.8) D4(-2.8,0) D5(-2.8,0.8) D6(-2.8,1.6) D7(-2.8,2.4) E1(-2,-2.4) E2(-2,-1.6) E3(-2,-0.8) E4(-2,0) E5(-2,0.8) E6(-2,1.6) E7(-2,2.4) F1(-1.2,-2.4) F2(-1.2,-1.6) F3(-1.2,-0.8) F4(-1.2,0) F5(-1.2,0.8) F6(-1.2,1.6) F7(-1.2,2.4) G1(-0.4,-2.4) G2(-0.4,-1.6) G3(-0.4,-0.8) G4(-0.4,0) G5(-0.4,0.8) G6(-0.4,1.6) G7(-0.4,2.4) H1(0.4,-2.4) H2(0.4,-1.6) H3(0.4,-0.8) H4(0.4,0) H5(0.4,0.8) H6(0.4,1.6) H7(0.4,2.4) J1(1.2,-2.4) J2(1.2,-1.6) J3(1.2,-0.8) J4(1.2,0) J5(1.2,0.8) J6(1.2,1.6) J7(1.2,2.4) K1(2,-2.4) K2(2,-1.6) K3(2,-0.8) K4(2,0) K5(2,0.8) K6(2,1.6) K7(2,2.4) L1(2.8,-2.4) L2(2.8,-1.6) L3(2.8,-0.8) L4(2.8,0) L5(2.8,0.8) L6(2.8,1.6) L7(2.8,2.4) M1(3.6,-2.4) M2(3.6,-1.6) M3(3.6,-0.8) M4(3.6,0) M5(3.6,0.8) M6(3.6,1.6) M7(3.6,2.4) N1(4.4,-2.4) N2(4.4,-1.6) N3(4.4,-0.8) N4(4.4,0) N5(4.4,0.8) N6(4.4,1.6) N7(4.4,2.4) P1(5.2,-2.4) P2(5.2,-1.6) P3(5.2,-0.8) P4(5.2,0) P5(5.2,0.8) P6(5.2,1.6) P7(5.2,2.4)
BGA210_16_9X8_1
  round 0.406 smd: A1(-8,-3.6) A2(-8,-2.8) A3(-8,-2) A4(-8,-1.2) A5(-8,-0.4) A6(-8,0.4) A7(-8,1.2) A8(-8,2) A9(-8,2.8) A10(-8,3.6) AA1(8,-3.6) AA2(8,-2.8) AA3(8,-2) AA4(8,-1.2) AA5(8,-0.4) AA6(8,0.4) AA7(8,1.2) AA8(8,2) AA9(8,2.8) AA10(8,3.6) B1(-7.2,-3.6) B2(-7.2,-2.8) B3(-7.2,-2) B4(-7.2,-1.2) B5(-7.2,-0.4) B6(-7.2,0.4) B7(-7.2,1.2) B8(-7.2,2) B9(-7.2,2.8) B10(-7.2,3.6) C1(-6.4,-3.6) C2(-6.4,-2.8) C3(-6.4,-2) C4(-6.4,-1.2) C5(-6.4,-0.4) C6(-6.4,0.4) C7(-6.4,1.2) C8(-6.4,2) C9(-6.4,2.8) C10(-6.4,3.6) D1(-5.6,-3.6) D2(-5.6,-2.8) D3(-5.6,-2) D4(-5.6,-1.2) D5(-5.6,-0.4) D6(-5.6,0.4) D7(-5.6,1.2) D8(-5.6,2) D9(-5.6,2.8) D10(-5.6,3.6) E1(-4.8,-3.6) E2(-4.8,-2.8) E3(-4.8,-2) E4(-4.8,-1.2) E5(-4.8,-0.4) E6(-4.8,0.4) E7(-4.8,1.2) E8(-4.8,2) E9(-4.8,2.8) E10(-4.8,3.6) F1(-4,-3.6) F2(-4,-2.8) F3(-4,-2) F4(-4,-1.2) F5(-4,-0.4) F6(-4,0.4) F7(-4,1.2) F8(-4,2) F9(-4,2.8) F10(-4,3.6) G1(-3.2,-3.6) G2(-3.2,-2.8) G3(-3.2,-2) G4(-3.2,-1.2) G5(-3.2,-0.4) G6(-3.2,0.4) G7(-3.2,1.2) G8(-3.2,2) G9(-3.2,2.8) G10(-3.2,3.6) H1(-2.4,-3.6) H2(-2.4,-2.8) H3(-2.4,-2) H4(-2.4,-1.2) H5(-2.4,-0.4) H6(-2.4,0.4) H7(-2.4,1.2) H8(-2.4,2) H9(-2.4,2.8) H10(-2.4,3.6) J1(-1.6,-3.6) J2(-1.6,-2.8) J3(-1.6,-2) J4(-1.6,-1.2) J5(-1.6,-0.4) J6(-1.6,0.4) J7(-1.6,1.2) J8(-1.6,2) J9(-1.6,2.8) J10(-1.6,3.6) K1(-0.8,-3.6) K2(-0.8,-2.8) K3(-0.8,-2) K4(-0.8,-1.2) K5(-0.8,-0.4) K6(-0.8,0.4) K7(-0.8,1.2) K8(-0.8,2) K9(-0.8,2.8) K10(-0.8,3.6) L1(0,-3.6) L2(0,-2.8) L3(0,-2) L4(0,-1.2) L5(0,-0.4) L6(0,0.4) L7(0,1.2) L8(0,2) L9(0,2.8) L10(0,3.6) M1(0.8,-3.6) M2(0.8,-2.8) M3(0.8,-2) M4(0.8,-1.2) M5(0.8,-0.4) M6(0.8,0.4) M7(0.8,1.2) M8(0.8,2) M9(0.8,2.8) M10(0.8,3.6) N1(1.6,-3.6) N2(1.6,-2.8) N3(1.6,-2) N4(1.6,-1.2) N5(1.6,-0.4) N6(1.6,0.4) N7(1.6,1.2) N8(1.6,2) N9(1.6,2.8) N10(1.6,3.6) P1(2.4,-3.6) P2(2.4,-2.8) P3(2.4,-2) P4(2.4,-1.2) P5(2.4,-0.4) P6(2.4,0.4) P7(2.4,1.2) P8(2.4,2) P9(2.4,2.8) P10(2.4,3.6) R1(3.2,-3.6) R2(3.2,-2.8) R3(3.2,-2) R4(3.2,-1.2) R5(3.2,-0.4) R6(3.2,0.4) R7(3.2,1.2) R8(3.2,2) R9(3.2,2.8) R10(3.2,3.6) T1(4,-3.6) T2(4,-2.8) T3(4,-2) T4(4,-1.2) T5(4,-0.4) T6(4,0.4) T7(4,1.2) T8(4,2) T9(4,2.8) T10(4,3.6) U1(4.8,-3.6) U2(4.8,-2.8) U3(4.8,-2) U4(4.8,-1.2) U5(4.8,-0.4) U6(4.8,0.4) U7(4.8,1.2) U8(4.8,2) U9(4.8,2.8) U10(4.8,3.6) V1(5.6,-3.6) V2(5.6,-2.8) V3(5.6,-2) V4(5.6,-1.2) V5(5.6,-0.4) V6(5.6,0.4) V7(5.6,1.2) V8(5.6,2) V9(5.6,2.8) V10(5.6,3.6) W1(6.4,-3.6) W2(6.4,-2.8) W3(6.4,-2) W4(6.4,-1.2) W5(6.4,-0.4) W6(6.4,0.4) W7(6.4,1.2) W8(6.4,2) W9(6.4,2.8) W10(6.4,3.6) Y1(7.2,-3.6) Y2(7.2,-2.8) Y3(7.2,-2) Y4(7.2,-1.2) Y5(7.2,-0.4) Y6(7.2,0.4) Y7(7.2,1.2) Y8(7.2,2) Y9(7.2,2.8) Y10(7.2,3.6)
